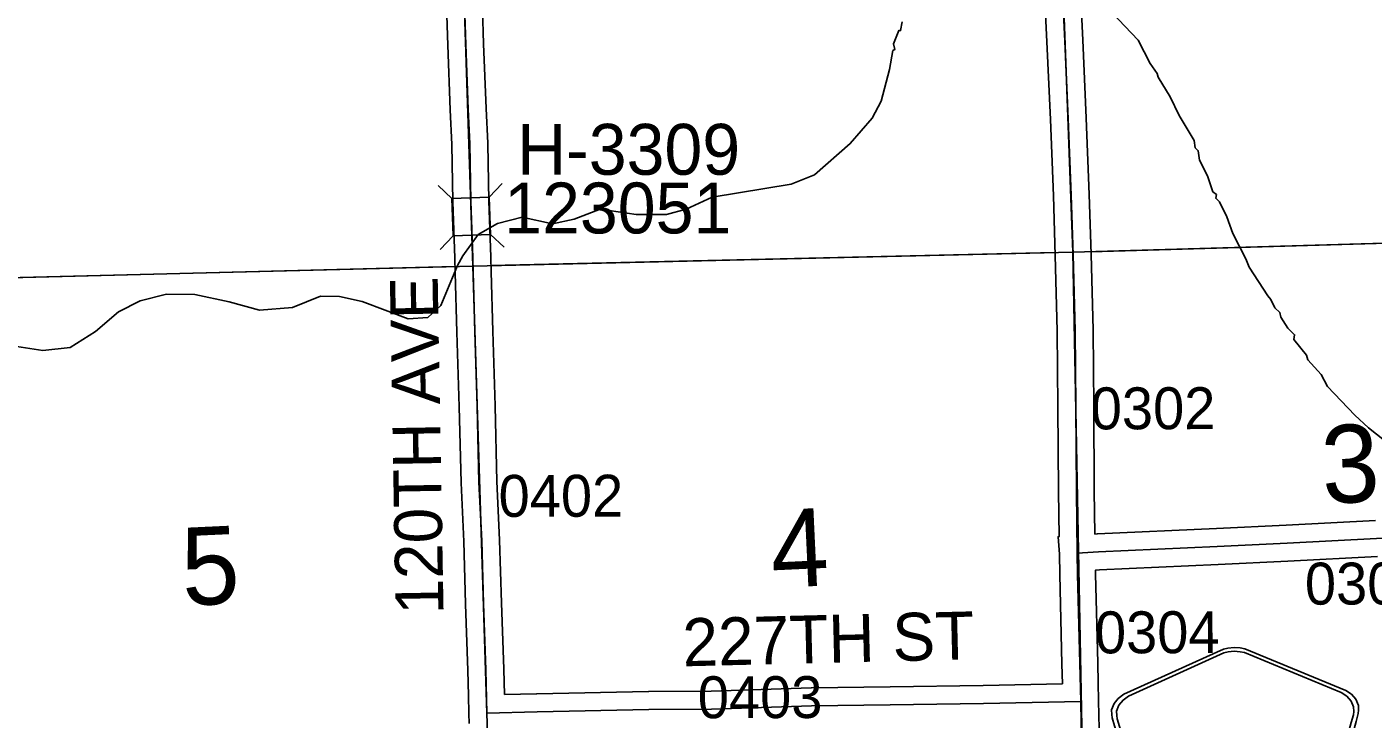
# Model space of a CAD drawing. Extents: x 128.7 to 185.5, y -21.4 to 12.6.
# Drawn here: x 135.429 to 137.678, y -8.408 to -7.251 of the extents above; entities that cross this region are included whole.
import ezdxf

# ---------------------------------------------------------------- set-up
doc = ezdxf.new("R2010")
doc.units = 0
for name, color, linetype in [('tdCoHydroRiver', 7, 'Continuous'), ('tdCoSecRdNmbr', 7, 'Continuous'), ('tdCoSecRdTxt', 7, 'Continuous'), ('tdCoSecRteBand', 7, 'Continuous'), ('tdCoSecRteCL', 7, 'Continuous'), ('tdCoSectLine', 7, 'Continuous'), ('tdCoSectLinePart', 7, 'Continuous'), ('tdCoSectNmbr', 7, 'Continuous'), ('tdCoShieldCoRteHrd', 7, 'Continuous'), ('tdCoStrucSec', 7, 'Continuous'), ('tdCoStrucSecCoName', 7, 'Continuous'), ('tdCoStrucSecFHWANum', 7, 'Continuous'), ('tdCoSurfAsphalt', 7, 'Continuous'), ('tdCoSurfGravel', 7, 'Continuous'), ('tdCoTwpBndry', 7, 'Continuous'), ('tdCoTwpBndryShd', 7, 'Continuous')]:
    doc.layers.add(name, color=color, linetype=linetype)

msp = doc.modelspace()

# ---------------------------------------------------------------- linework, layer by layer
at = {"layer": 'tdCoHydroRiver'}
for points in [[(137.2411, -7.2274), (137.2851, -7.2734), (137.3053, -7.3122), (137.3169, -7.3292), (137.3186, -7.3355), (137.3386, -7.368), (137.3537, -7.3991), (137.3787, -7.4409), (137.3807, -7.4535), (137.3856, -7.4581), (137.3876, -7.4738), (137.4011, -7.5002), (137.4098, -7.5267), (137.4163, -7.5313), (137.4149, -7.5376), (137.4214, -7.5437), (137.4332, -7.5686), (137.4436, -7.5967), (137.4654, -7.6386), (137.4705, -7.6527), (137.502, -7.7006), (137.507, -7.7068), (137.5137, -7.7208), (137.5218, -7.7284), (137.5237, -7.7362), (137.5353, -7.7548), (137.5467, -7.7655), (137.5453, -7.7734), (137.5667, -7.7996), (137.5685, -7.8074), (137.5913, -7.832), (137.6014, -7.8522), (137.6471, -7.8997), (137.6699, -7.921), (137.7637, -7.9954)], [(135.4121, -7.7854), (135.4552, -7.7919), (135.5011, -7.7871), (135.5432, -7.7604), (135.582, -7.7275), (135.618, -7.7089), (135.6618, -7.698), (135.7092, -7.6981), (135.7664, -7.7106), (135.8173, -7.7247), (135.8724, -7.7199), (135.9192, -7.7011), (135.9508, -7.7017), (135.9889, -7.7099), (136.0655, -7.7391), (136.0986, -7.7365), (136.1201, -7.7169), (136.148, -7.6497), (136.157, -7.6337), (136.1827, -7.5981), (136.2152, -7.5798), (136.2559, -7.569), (136.3068, -7.5801), (136.3428, -7.5726), (136.3865, -7.5555), (136.4468, -7.5647), (136.4973, -7.5647), (136.5301, -7.5558), (136.5737, -7.5355), (136.7056, -7.514), (136.7445, -7.4986), (136.8044, -7.4462), (136.841, -7.404), (136.8559, -7.3752), (136.87, -7.3226), (136.8754, -7.2909), (136.8785, -7.2892), (136.8766, -7.2798), (136.8854, -7.2575), (136.8885, -7.2574), (136.8912, -7.2431)]]:
    msp.add_lwpolyline(points, dxfattribs=at)
at = {"layer": 'tdCoSecRteBand'}
for points in [[(136.2266, -8.3667), (136.2803, -8.3654), (136.2803, -8.3654), (136.2804, -8.3654), (136.4673, -8.3614), (136.4676, -8.3614), (136.4678, -8.3614), (136.5717, -8.3609), (136.7388, -8.3555), (136.739, -8.3555), (136.7393, -8.3555), (136.8708, -8.3538), (137.0265, -8.3515), (137.1586, -8.3487), (137.1579, -8.3157), (137.1542, -8.1663), (137.1542, -8.1662), (137.1542, -8.1661), (137.1536, -8.132), (137.1516, -8.1029), (137.1532, -8.1027), (137.152, -8.0272), (137.152, -8.0271), (137.152, -8.027), (137.151, -7.8861), (137.151, -7.8861), (137.151, -7.8861), (137.1502, -7.7589), (137.1468, -7.6331), (137.1436, -7.5334), (137.1387, -7.4061), (137.1327, -7.2765), (137.1266, -7.1478)], [(137.1865, -7.1452), (137.1927, -7.2737), (137.1927, -7.2737), (137.1927, -7.2737), (137.1986, -7.4034), (137.1986, -7.4035), (137.1986, -7.4037), (137.2035, -7.5311), (137.2035, -7.5312), (137.2036, -7.5313), (137.2068, -7.6312), (137.2068, -7.6313), (137.2068, -7.6314), (137.2102, -7.7576), (137.2102, -7.7579), (137.2102, -7.7583), (137.211, -7.8857), (137.2119, -8.0264), (137.2131, -8.0986), (137.2167, -8.0983), (137.2171, -8.0983), (137.2174, -8.0983), (137.4159, -8.0892), (137.5325, -8.0838), (137.6819, -8.0761)], [(136.1676, -8.415), (136.1672, -8.3982), (136.1665, -8.3683), (136.1666, -8.3683), (136.1656, -8.3262), (136.1617, -8.2154), (136.1617, -8.2153), (136.1617, -8.2153), (136.1585, -8.1109), (136.1541, -8.013), (136.1541, -8.0127), (136.154, -8.0123), (136.1511, -7.8862), (136.1471, -7.7615), (136.1471, -7.7615), (136.1471, -7.7614), (136.1444, -7.6619), (136.1437, -7.6377), (136.1405, -7.5434), (136.1405, -7.5431), (136.1405, -7.5429), (136.1388, -7.4479), (136.1361, -7.3901), (136.1361, -7.39), (136.1361, -7.3899), (136.1319, -7.2819), (136.1319, -7.2817), (136.1319, -7.2816), (136.1282, -7.165)], [(136.1881, -7.1632), (136.1918, -7.2796), (136.196, -7.3874), (136.1987, -7.4455), (136.1987, -7.4459), (136.1987, -7.4464), (136.2005, -7.5416), (136.2037, -7.6358), (136.2037, -7.6359), (136.2037, -7.636), (136.2043, -7.6602), (136.2071, -7.7597), (136.2111, -7.8844), (136.2111, -7.8845), (136.2111, -7.8847), (136.214, -8.0106), (136.2184, -8.1084), (136.2185, -8.1086), (136.2185, -8.1089), (136.2217, -8.2133), (136.2256, -8.3242), (136.2256, -8.3244), (136.2256, -8.3247), (136.2266, -8.3667)], [(137.6849, -8.136), (137.5355, -8.1437), (137.5354, -8.1437), (137.5354, -8.1437), (137.4187, -8.1491), (137.4187, -8.1491), (137.4187, -8.1491), (137.2205, -8.1582), (137.2141, -8.1587), (137.2141, -8.1602), (137.2142, -8.165), (137.2179, -8.3143), (137.2179, -8.3143), (137.2179, -8.3144), (137.2186, -8.3473), (137.2186, -8.3473), (137.2193, -8.3773), (137.2208, -8.4475)]]:
    msp.add_lwpolyline(points, dxfattribs=at)
at = {"layer": 'tdCoSecRteCL'}
for points in [[(137.1836, -8.1307), (137.182, -8.0268), (137.181, -7.8859), (137.1802, -7.7584), (137.1768, -7.6322), (137.1736, -7.5323), (137.1686, -7.4048), (137.1627, -7.2751), (137.1566, -7.1464), (137.1521, -7.0093), (137.1467, -6.8549), (137.145, -6.8046), (137.1405, -6.6591), (137.139, -6.6181)], [(136.1972, -8.3975), (136.1956, -8.3253), (136.1917, -8.2143), (136.1885, -8.1098), (136.184, -8.0116), (136.1811, -7.8854), (136.1771, -7.7606), (136.1744, -7.661), (136.1737, -7.6368), (136.1705, -7.5423), (136.1687, -7.4469), (136.166, -7.3887), (136.1618, -7.2807), (136.1581, -7.164), (136.1549, -7.0185), (136.1483, -6.8772), (136.1446, -6.7438), (136.141, -6.6467)], [(137.1836, -8.1307), (137.2188, -8.1283), (137.4173, -8.1192), (137.534, -8.1137), (137.6834, -8.1061), (137.9088, -8.0955), (138.128, -8.0881), (138.1845, -8.0868), (138.279, -8.0846), (138.3881, -8.0855), (138.4725, -8.0861), (138.5876, -8.0858)], [(137.1893, -8.378), (137.1879, -8.315), (137.1842, -8.1656), (137.1836, -8.1307)], [(136.1972, -8.3975), (136.281, -8.3954), (136.468, -8.3914), (136.5723, -8.3909), (136.7397, -8.3855), (136.8712, -8.3838), (137.027, -8.3815), (137.1893, -8.378)], [(137.2036, -9.022), (137.2019, -8.8967), (137.2017, -8.879), (137.2017, -8.8783), (137.2017, -8.8783), (137.1982, -8.7404), (137.1943, -8.5861), (137.1908, -8.4482), (137.1893, -8.378)], [(136.2055, -8.6468), (136.2038, -8.6121), (136.2018, -8.5302), (136.1976, -8.4143), (136.1972, -8.3975)]]:
    msp.add_lwpolyline(points, dxfattribs=at)
at = {"layer": 'tdCoSectLine'}
for points in [[(137.1386, -6.6181), (137.1762, -7.6276)], [(136.1406, -6.6467), (136.1739, -7.6508)], [(137.1762, -7.6276), (138.1783, -7.5984)], [(136.1739, -7.6508), (137.1762, -7.6276)], [(137.1762, -7.6276), (137.1949, -8.626)], [(135.1725, -7.6763), (136.1739, -7.6508)], [(136.1739, -7.6508), (136.2051, -8.6468)]]:
    msp.add_lwpolyline(points, dxfattribs=at)
at = {"layer": 'tdCoSectLinePart'}
for points in [[(137.2062, -7.6268), (138.1783, -7.5984)], [(136.204, -7.6501), (137.1462, -7.6283)], [(135.2022, -7.6756), (136.144, -7.6516)]]:
    msp.add_lwpolyline(points, dxfattribs=at)
at = {"layer": 'tdCoShieldCoRteHrd'}
for points in [[(137.3329, -8.7002), (137.246, -8.4188), (137.2419, -8.4057), (137.2411, -8.3998), (137.2409, -8.392), (137.245, -8.3816), (137.2521, -8.373), (137.2616, -8.3661), (137.4276, -8.2909), (137.4351, -8.2891), (137.4455, -8.288), (137.4559, -8.2887), (137.4635, -8.2903), (137.632, -8.3597), (137.6417, -8.3662), (137.6491, -8.3745), (137.6535, -8.3848), (137.6536, -8.3926), (137.653, -8.3985), (137.6494, -8.4117), (137.5724, -8.696)], [(137.3386, -8.6937), (137.2541, -8.4199), (137.2502, -8.4073), (137.2494, -8.4017), (137.2492, -8.3942), (137.2531, -8.3842), (137.26, -8.376), (137.2691, -8.3694), (137.4284, -8.2971), (137.4356, -8.2954), (137.4456, -8.2944), (137.4556, -8.2951), (137.4628, -8.2965), (137.6246, -8.3632), (137.6339, -8.3694), (137.641, -8.3775), (137.6453, -8.3873), (137.6454, -8.3948), (137.6448, -8.4004), (137.6413, -8.4131), (137.5664, -8.6898)]]:
    msp.add_lwpolyline(points, close=True, dxfattribs=at)
at = {"layer": 'tdCoStrucSec'}
for p, q in [((136.1386, -7.5377), (136.1157, -7.5163)), ((136.2012, -7.5356), (136.2225, -7.5127)), ((136.1407, -7.6002), (136.1194, -7.6231)), ((136.2033, -7.5981), (136.2262, -7.6195))]:
    msp.add_line(p, q, dxfattribs=at)
msp.add_lwpolyline([(136.1407, -7.6002), (136.1386, -7.5377), (136.2012, -7.5356), (136.2033, -7.5981)], close=True, dxfattribs=at)
at = {"layer": 'tdCoSurfAsphalt'}
msp.add_lwpolyline([(137.2036, -9.022), (137.2019, -8.8967), (137.2017, -8.879), (137.2017, -8.8783), (137.2017, -8.8783), (137.1982, -8.7404), (137.1943, -8.5861), (137.1908, -8.4482), (137.1893, -8.378), (137.1879, -8.315), (137.1842, -8.1656), (137.1836, -8.1307), (137.182, -8.0268), (137.181, -7.8859), (137.1802, -7.7584), (137.1768, -7.6322), (137.1736, -7.5323), (137.1686, -7.4048), (137.1627, -7.2751), (137.1566, -7.1464)], dxfattribs=at)
at = {"layer": 'tdCoSurfGravel'}
for points in [[(136.1744, -7.661), (136.1737, -7.6368), (136.1705, -7.5423), (136.1687, -7.4469), (136.166, -7.3887), (136.1618, -7.2807), (136.1581, -7.164), (136.1549, -7.0185), (136.1483, -6.8772), (136.1446, -6.7438), (136.141, -6.6467), (136.1406, -6.6361), (136.1335, -6.4856), (136.1276, -6.3542), (136.1226, -6.2341), (136.1167, -6.0842), (136.111, -5.95), (136.1059, -5.8191), (136.1004, -5.6819), (136.096, -5.5549), (136.0903, -5.4134), (136.0859, -5.2849), (136.0837, -5.2442), (136.0844, -5.2336)], [(136.2055, -8.6468), (136.2038, -8.6121), (136.2018, -8.5302), (136.1976, -8.4143), (136.1972, -8.3975), (136.1956, -8.3253), (136.1917, -8.2143), (136.1885, -8.1098), (136.184, -8.0116), (136.1811, -7.8854), (136.1771, -7.7606), (136.1744, -7.661)], [(137.1836, -8.1307), (137.2188, -8.1283), (137.4173, -8.1192), (137.534, -8.1137), (137.6834, -8.1061), (137.9088, -8.0955), (138.128, -8.0881), (138.1845, -8.0868)], [(136.1972, -8.3975), (136.281, -8.3954), (136.468, -8.3914), (136.5723, -8.3909), (136.7397, -8.3855), (136.8712, -8.3838), (137.027, -8.3815), (137.1893, -8.378)]]:
    msp.add_lwpolyline(points, dxfattribs=at)
at = {"layer": 'tdCoTwpBndry'}
for points in [[(140.1462, -7.549), (139.1499, -7.567), (138.1783, -7.5984), (137.2062, -7.6268)], [(137.1463, -7.6283), (136.2041, -7.6501)], [(136.1439, -7.6516), (135.2025, -7.6756)]]:
    msp.add_lwpolyline(points, dxfattribs=at)
at = {"layer": 'tdCoTwpBndryShd'}
msp.add_lwpolyline([(150.395, -13.7476), (150.378, -13.2238), (150.3466, -12.2212), (150.3134, -11.2212), (150.2794, -10.2174), (150.245, -9.219), (150.2118, -8.2199), (150.1854, -7.2186), (149.1912, -7.251), (148.1861, -7.2877), (147.1862, -7.3236), (146.1796, -7.3579), (145.1769, -7.3938), (144.1761, -7.4248), (143.1728, -7.4558), (142.1753, -7.4874), (141.1678, -7.5201), (140.1762, -7.5484), (139.1499, -7.567), (138.1783, -7.5984), (137.1762, -7.6276), (136.1739, -7.6508), (135.1725, -7.6763), (134.1612, -7.6994)], dxfattribs=at)

# ---------------------------------------------------------------- texts
at = {"layer": 'tdCoSecRdNmbr'}
for s, rotation, p in [('0302', 0.1043, (137.2061, -7.9236)), ('0402', 0.1036, (136.2168, -8.0698)), ('0303', 0.1046, (137.5639, -8.2164)), ('0304', 0.1043, (137.2131, -8.2978)), ('0403', 0.1038, (136.5496, -8.4062))]:
    msp.add_text(s, height=0.07, rotation=rotation, dxfattribs=at).set_placement(p)
at = {"layer": 'tdCoSecRdTxt'}
for s, rotation, p in [('120TH AVE', 91, (136.1249, -8.2324)), ('227TH ST', 1.418, (136.5249, -8.3196))]:
    msp.add_text(s, height=0.08, rotation=rotation, dxfattribs=at).set_placement(p)
at = {"layer": 'tdCoSectNmbr'}
for s, rotation, p in [('3', 2.6569, (137.5942, -8.048)), ('4', 2.6562, (136.674, -8.1887)), ('5', 2.6555, (135.6896, -8.2183))]:
    msp.add_text(s, height=0.13, rotation=rotation, dxfattribs=at).set_placement(p)
at = {"layer": 'tdCoStrucSecCoName'}
msp.add_text('H-3309', height=0.085, dxfattribs=at).set_placement((136.2475, -7.4983))
at = {"layer": 'tdCoStrucSecFHWANum'}
msp.add_text('123051', height=0.085, dxfattribs=at).set_placement((136.2262, -7.5963))

doc.saveas('drawing.dxf')
